(* Logix 5000 project; controller MyFirstProject_iC7 vendor 1 type 14 code 244 rev 36.11; software revision 36.00 *)

TASK MainTask (continuous, watchdog 500 ms) : MainProgram
TASK SafetyTask (periodic, rate 20 ms, priority 10, watchdog 20 ms, safety) : SafetyProgram

MODULES
   Local : vendor 1 type 14 code 244 (5069 0, rev 36.11)
      My_iC7_Drive : vendor 97 type 12 code 4354 (Ethernet 192.168.2.11, rev 1.2, StandardDataDriven RPI 20 ms)   // This is the iC7 drive for demonstration purpose.
END_MODULES

TYPE Read_iC_Speed_Profile :   // Status word and main actual value definition based on Danfoss iC speed profile
STRUCT
   BIT_00_CTRL_RDY : BOOL;   // 0=Control not ready, 1=Control ready
   BIT_01_DRV_RDY : BOOL;   // 0=Drive not ready, 1=Drive ready
   BIT_02_COAST_RDY : BOOL;   // 0=Motor coasted, 1=Motor control enabled
   BIT_03_FAULT : BOOL;   // 0=No error, 1=Fault
   BIT_04_RESERVED : BOOL;   // Reserved
   BIT_05_RESERVED : BOOL;   // Reserved
   BIT_06_RESERVED : BOOL;   // Reserved
   BIT_07_WARNING : BOOL;   // 0=No warning, 1=Warning
   BIT_08_RUNNING_REF : BOOL;   // 0=Speed <> reference, 1=Speed=reference
   BIT_09_CTRL_SOURCE : BOOL;   // 0=Local operation, 1=Bus control
   BIT_10_F_LIMIT_OK : BOOL;   // 0=Out of frequency limit, 1=Frequency limit ok
   BIT_11_IN_OPR : BOOL;   // 0=No operation, 1=In operation
   BIT_12_INTERMITTED : BOOL;   // 0=No intermitted problem, 1=Intermitted problem
   BIT_13_RESERVED : BOOL;   // Reserved
   BIT_14_USER : BOOL;   // Reserved
   BIT_15_USER : BOOL;   // Reserved
   MAV : INT;   // Main actual value (Speed) +-200% in raw. 0 - 16384(0x0 to 0x4000) forward. 16385 - 32768(0x4001 to 0x8000) reverse
END_STRUCT
END_TYPE

TYPE Write_iC_Speed_Profile :   // Control word and main reference value definition based on Danfoss iC speed profile
STRUCT
   BIT_00_PRESET_REF_1 : BOOL;   // 0=Reference value, 1=Selection LSB
   BIT_01_PRESET_REF_2 : BOOL;   // 0=Reference value, 1=Selection MSB
   BIT_02_RESERVED : BOOL;   // Reserved
   BIT_03_COAST_INV : BOOL;   // 0=Coasting, 1=No coasting
   BIT_04_RAMP_QSTP : BOOL;   // 0=Quick stop, 1=Ramp
   BIT_05_RAMP_HLD : BOOL;   // 0=Hold output frequency, 1=Use ramp
   BIT_06_START : BOOL;   // 0=Ramp stop, 1=Start
   BIT_07_FAULT_ACK : BOOL;   // 0=No function, 1=Reset
   BIT_08_JOG : BOOL;   // 0=No function, 1=Jog
   BIT_09_RAMP_1_2 : BOOL;   // 0=Ramp 1, 1=Ramp 2
   BIT_10_DATA_VALID : BOOL;   // 0=Don't use CTW, 1= Use CTW
   BIT_11_RESERVED : BOOL;   // Reserved
   BIT_12_USER : BOOL;   // User defined
   BIT_13_USER : BOOL;   // User defined
   BIT_14_USER : BOOL;   // User defined
   BIT_15_USER : BOOL;   // User defined
   MRV : INT;   // Main Actual Value read from Drive -200.0 to 200.00%
END_STRUCT
END_TYPE

ADD_ON_INSTRUCTION iC7_Basic   (* revision 0.1, vendor Danfoss *)
// Basic control and monitoring Add-On Instruction for the Danfoss iC7 frequency converters
VAR_INPUT
   COAST_INV : BOOL; {visible}   // 0=Coast stop command given; 1=Motor is in normal operation (do nothing)
   RUN : BOOL; {visible}   // 0=Motor ramp stop command; 1=Motor ramp start command
   REVERSE : BOOL; {visible}   // 0=Motor operating in forward direction; 1=Motor operating in reverse direction
   Q_STOP : BOOL; {visible}   // 0=Motor is in normal operation (do nothing); 1=Quick stop command given
   RESET : BOOL; {visible}   // 0=Do nothing; 1=Reset command for fault reset is given
   REF_VALUE : REAL; {visible}   // Reference speed setpoint (MRV) = -200.0% to 200.0%. Depends on 5.8.3.4 Absolute Ref. limit
END_VAR
VAR_OUTPUT
   READY : BOOL; {access Read Only, visible}   // 0=Drive is not ready to start the motor; 1=Drive is ready to start and control the motor
   FAULT : BOOL; {access Read Only, visible}   // 0=No fault(s) are present on the drive; 1=At least one fault is present on the drive
   WARNING : BOOL; {access Read Only, visible}   // 0=No warning(s) are present on the drive; 1=At least one warning is present on the drive
   RUNNING : BOOL; {access Read Only, visible}   // 0=Motor not magnetized and operational; 1=Motor magnetized and operational
   RUN_ON_REF : BOOL; {access Read Only, visible}   // 0=Requested reference motor speed not reached yet; 1=Motor speed is operating on requsted reference motor speed
   MAV : REAL; {access Read Only, visible}   // Main Actual Value read from Drive -200.0 to 200.00%
END_VAR
VAR_IN_OUT
   Data_IN : SINT[4]; {required}   // Controller tags from drive (Data In)
   Data_OUT : SINT[4]; {required}   // Controller tags to drive (Data Out)
END_VAR
VAR
   C_16384_To_Percent : REAL := 0.0061035156; {access None}   // Convert from MAV to percentage
   C_Percent_To_16384 : REAL := 163.84; {access None}   // Convert from percentage to MRV
   false : BOOL; {access None}   // Always FALSE
   true : BOOL := 1; {access None}   // Always TRUE
   Ref_Value_Tmp : DINT; {access None}   // Temporary value for MAV calculation
   Calc_Slope_Forward : REAL := 163.835; {access None}   // Constant for calculation from REAL to DINT in forward direction
   Calc_Slope_Reverse : REAL := 163.84; {access None}   // Constant for calculation from REAL to DINT in reverse direction
   ADR_PROFILE_I : Read_iC_Speed_Profile; {access None}   // Input address for data from the drive. Must be as per iC profile UDT 'Read_iC_Speed_Profile'
   ADR_PROFILE_Q : Write_iC_Speed_Profile; {access None}   // Output address for data to the drive. Must be as per iC profile UDT 'Write_iC_Speed_Profile'
   Start_Ons : BOOL; {access None}   // Start one-shot command
END_VAR

ROUTINE Logic   (* ladder *)
// Danfoss Drives iC Series Add-On Instruction (AOI) for basic motor control and monitoring
// Valid for Allen-Bracley Logix 5000 series CPU's.
// Block handles communication with an iC Series drive trough Ethernet/IP. This AOI requires iC Speed Profile to be selected in HW configuration of the drive.
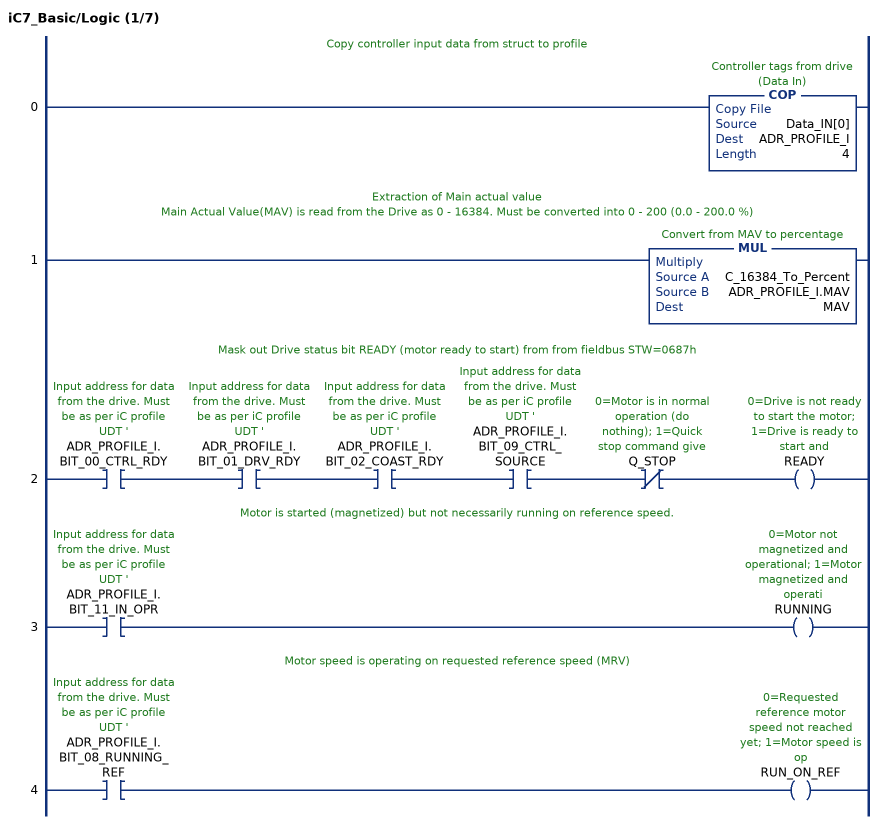
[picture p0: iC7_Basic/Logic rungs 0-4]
   // Copy controller input data from struct to profile
   0: COP(Data_IN[0],ADR_PROFILE_I,4);
   // Extraction of Main actual value
   // Main Actual Value(MAV) is read from the Drive as 0 - 16384. Must be converted into 0 - 200 (0.0 - 200.0 %)
   1: MUL(C_16384_To_Percent,ADR_PROFILE_I.MAV,MAV);
   // Mask out Drive status bit READY (motor ready to start) from from fieldbus STW=0687h
   2: XIC(ADR_PROFILE_I.BIT_00_CTRL_RDY)XIC(ADR_PROFILE_I.BIT_01_DRV_RDY)XIC(ADR_PROFILE_I.BIT_02_COAST_RDY)XIC(ADR_PROFILE_I.BIT_09_CTRL_SOURCE)XIO(Q_STOP)OTE(READY);
   // Motor is started (magnetized) but not necessarily running on reference speed.
   3: XIC(ADR_PROFILE_I.BIT_11_IN_OPR)OTE(RUNNING);
   // Motor speed is operating on requested reference speed (MRV)
   4: XIC(ADR_PROFILE_I.BIT_08_RUNNING_REF)OTE(RUN_ON_REF);
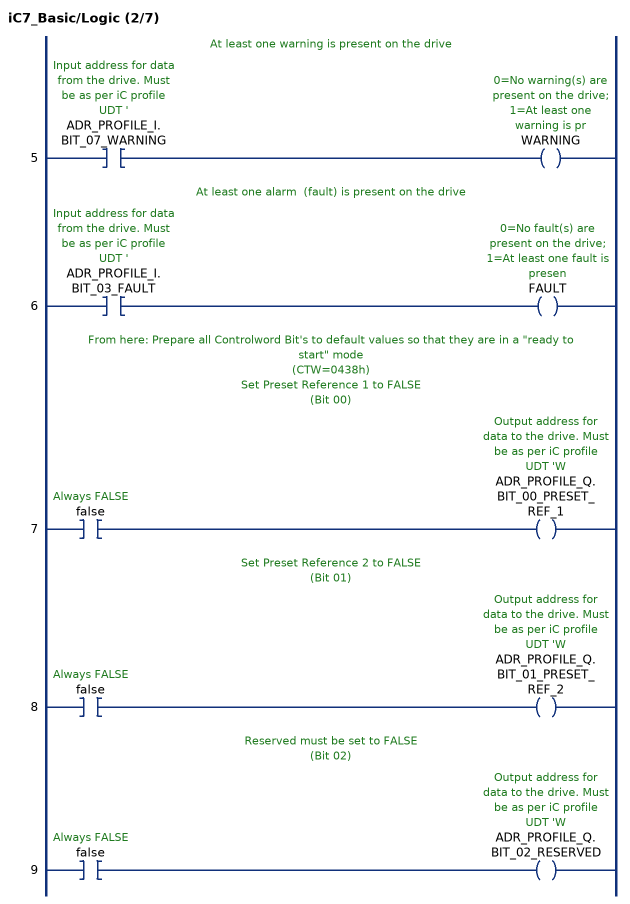
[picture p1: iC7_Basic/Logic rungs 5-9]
   // At least one warning is present on the drive
   5: XIC(ADR_PROFILE_I.BIT_07_WARNING)OTE(WARNING);
   // At least one alarm  (fault) is present on the drive
   6: XIC(ADR_PROFILE_I.BIT_03_FAULT)OTE(FAULT);
   // From here: Prepare all Controlword Bit's to default values so that they are in a "ready to start" mode
   // (CTW=0438h)
   // Set Preset Reference 1 to FALSE
   // (Bit 00)
   7: XIC(false)OTE(ADR_PROFILE_Q.BIT_00_PRESET_REF_1);
   // Set Preset Reference 2 to FALSE
   // (Bit 01)
   8: XIC(false)OTE(ADR_PROFILE_Q.BIT_01_PRESET_REF_2);
   // Reserved must be set to FALSE
   // (Bit 02)
   9: XIC(false)OTE(ADR_PROFILE_Q.BIT_02_RESERVED);
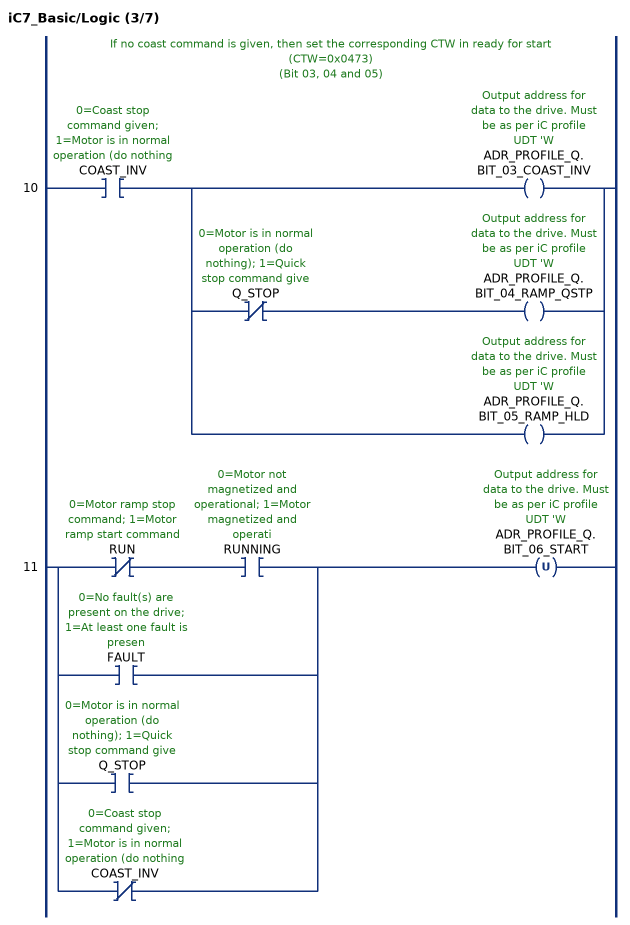
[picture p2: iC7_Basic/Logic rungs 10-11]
   // If no coast command is given, then set the corresponding CTW in ready for start (CTW=0x0473)
   // (Bit 03, 04 and 05)
   10: XIC(COAST_INV)[OTE(ADR_PROFILE_Q.BIT_03_COAST_INV) ,[XIO(Q_STOP) OTE(ADR_PROFILE_Q.BIT_04_RAMP_QSTP) ,OTE(ADR_PROFILE_Q.BIT_05_RAMP_HLD) ] ];
   11: [XIO(RUN) XIC(RUNNING) ,[XIC(FAULT) ,[XIC(Q_STOP) ,XIO(COAST_INV) ] ] ]OTU(ADR_PROFILE_Q.BIT_06_START);
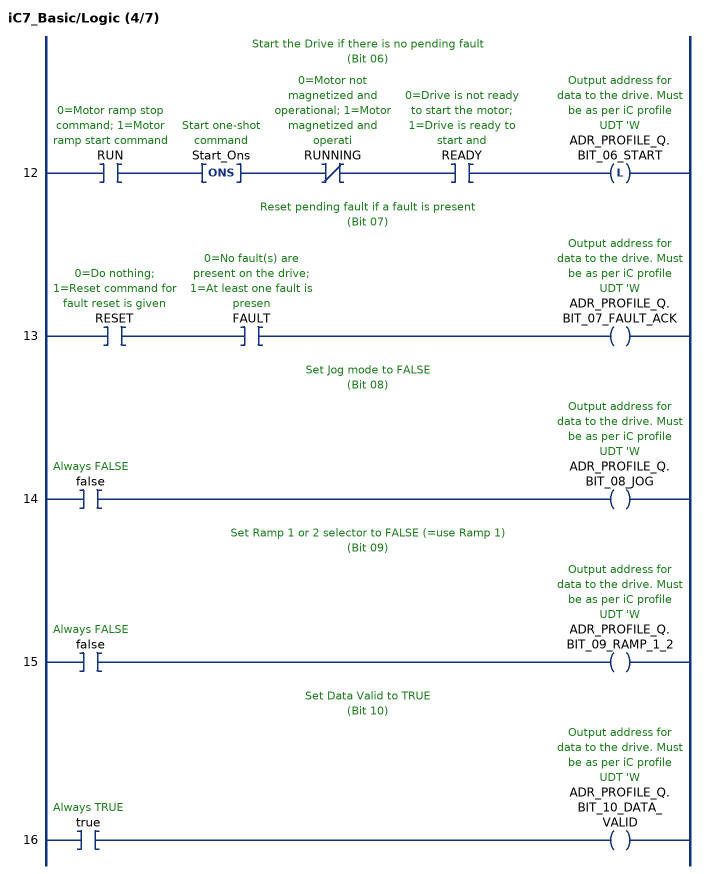
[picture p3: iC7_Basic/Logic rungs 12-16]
   // Start the Drive if there is no pending fault
   // (Bit 06)
   12: XIC(RUN)ONS(Start_Ons)XIO(RUNNING)XIC(READY)OTL(ADR_PROFILE_Q.BIT_06_START);
   // Reset pending fault if a fault is present
   // (Bit 07)
   13: XIC(RESET)XIC(FAULT)OTE(ADR_PROFILE_Q.BIT_07_FAULT_ACK);
   // Set Jog mode to FALSE
   // (Bit 08)
   14: XIC(false)OTE(ADR_PROFILE_Q.BIT_08_JOG);
   // Set Ramp 1 or 2 selector to FALSE (=use Ramp 1)
   // (Bit 09)
   15: XIC(false)OTE(ADR_PROFILE_Q.BIT_09_RAMP_1_2);
   // Set Data Valid to TRUE
   // (Bit 10)
   16: XIC(true)OTE(ADR_PROFILE_Q.BIT_10_DATA_VALID);
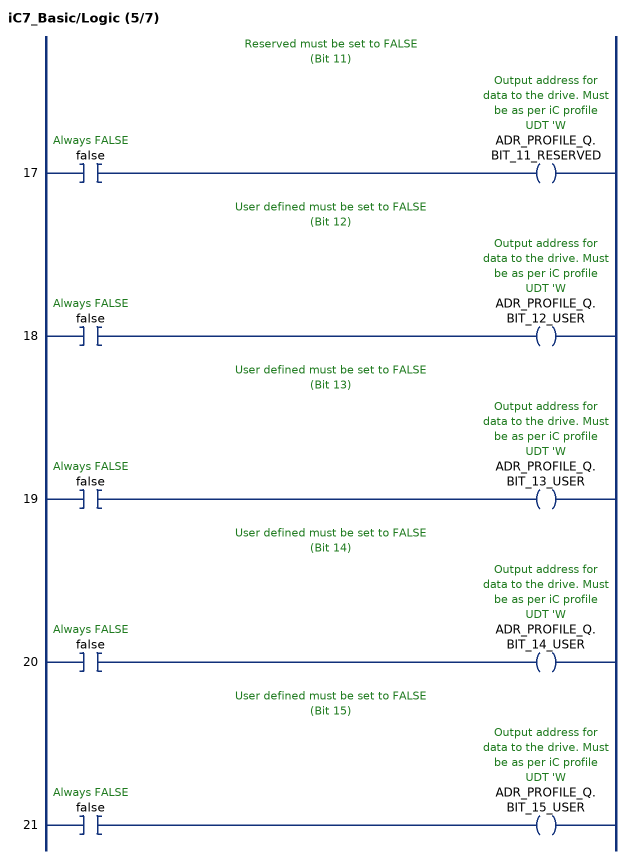
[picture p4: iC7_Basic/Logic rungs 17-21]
   // Reserved must be set to FALSE
   // (Bit 11)
   17: XIC(false)OTE(ADR_PROFILE_Q.BIT_11_RESERVED);
   // User defined must be set to FALSE
   // (Bit 12)
   18: XIC(false)OTE(ADR_PROFILE_Q.BIT_12_USER);
   // User defined must be set to FALSE
   // (Bit 13)
   19: XIC(false)OTE(ADR_PROFILE_Q.BIT_13_USER);
   // User defined must be set to FALSE
   // (Bit 14)
   20: XIC(false)OTE(ADR_PROFILE_Q.BIT_14_USER);
   // User defined must be set to FALSE
   // (Bit 15)
   21: XIC(false)OTE(ADR_PROFILE_Q.BIT_15_USER);
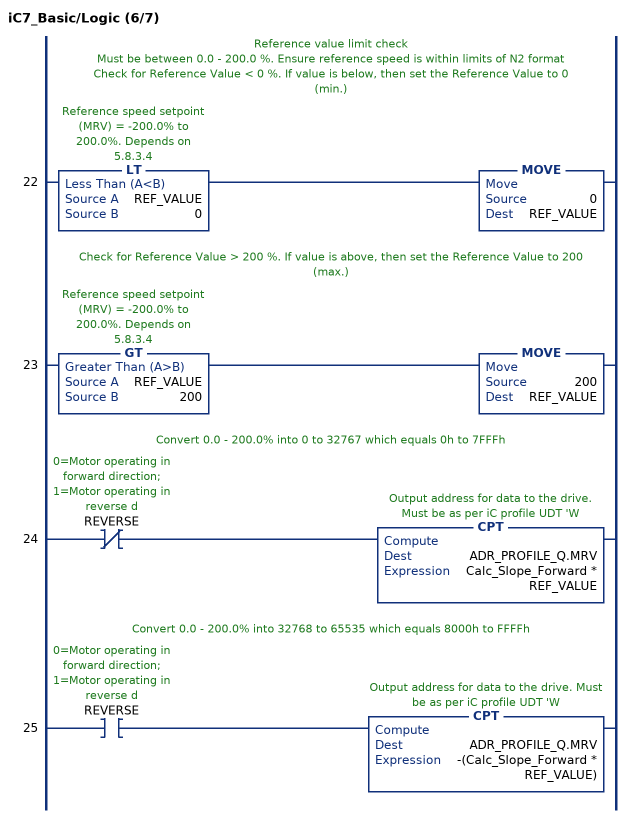
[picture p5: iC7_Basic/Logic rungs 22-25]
   // Reference value limit check
   // Must be between 0.0 - 200.0 %. Ensure reference speed is within limits of N2 format
   // Check for Reference Value < 0 %. If value is below, then set the Reference Value to 0 (min.)
   22: LT(REF_VALUE,0)MOVE(0,REF_VALUE);
   // Check for Reference Value > 200 %. If value is above, then set the Reference Value to 200 (max.)
   23: GT(REF_VALUE,200)MOVE(200,REF_VALUE);
   // Convert 0.0 - 200.0% into 0 to 32767 which equals 0h to 7FFFh
   24: XIO(REVERSE)CPT(ADR_PROFILE_Q.MRV,Calc_Slope_Forward * REF_VALUE);
   // Convert 0.0 - 200.0% into 32768 to 65535 which equals 8000h to FFFFh
   25: XIC(REVERSE)CPT(ADR_PROFILE_Q.MRV,-(Calc_Slope_Forward * REF_VALUE));
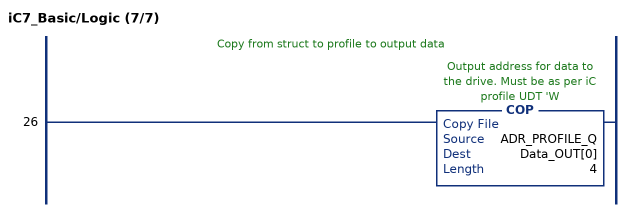
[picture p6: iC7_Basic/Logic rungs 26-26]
   // Copy from struct to profile to output data
   26: COP(ADR_PROFILE_Q,Data_OUT[0],4);
END_ROUTINE
END_ADD_ON_INSTRUCTION

PROGRAM MainProgram   (* main routine MainRoutine *)
VAR
   Motor_1 : iC7_Basic;
END_VAR

ROUTINE MainRoutine   (* ladder *)
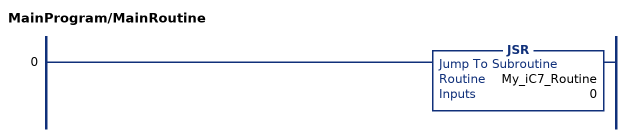
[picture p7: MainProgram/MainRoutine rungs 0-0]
   0: JSR(My_iC7_Routine,0);
END_ROUTINE

ROUTINE My_iC7_Routine   (* ladder *)
// Routine to execute the iC7 AOI.
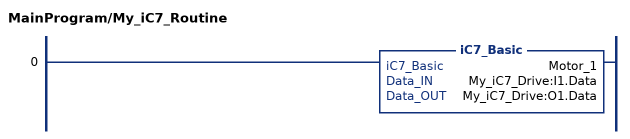
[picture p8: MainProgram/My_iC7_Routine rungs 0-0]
   0: iC7_Basic(Motor_1,My_iC7_Drive:I1.Data,My_iC7_Drive:O1.Data);
END_ROUTINE
END_PROGRAM

PROGRAM SafetyProgram   (* main routine MainRoutine, safety *)

ROUTINE MainRoutine   (* ladder *)
END_ROUTINE
END_PROGRAM
